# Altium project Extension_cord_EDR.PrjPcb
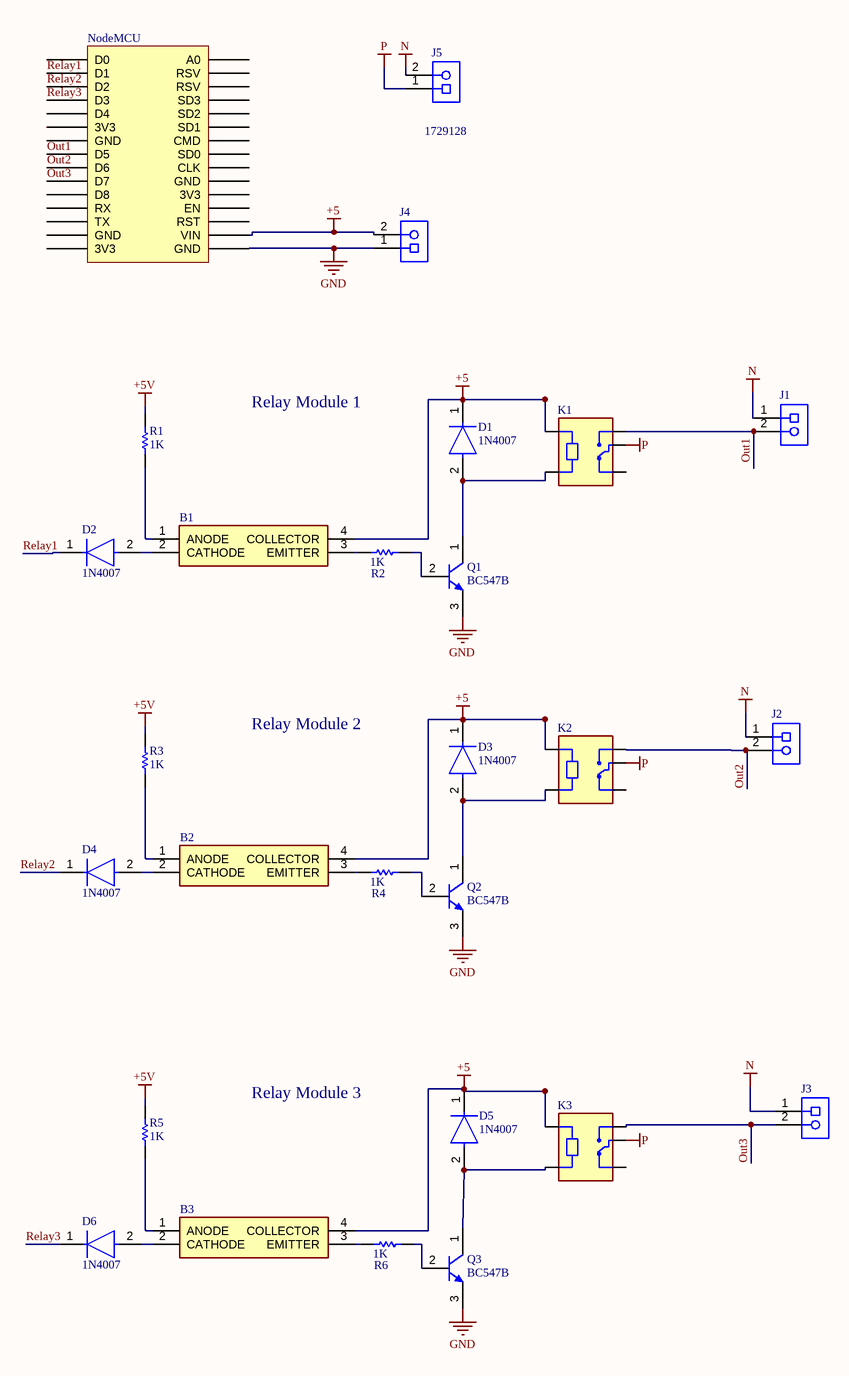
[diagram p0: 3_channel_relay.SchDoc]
1 sheet, 27 parts. Net scope: global (net labels, ports and power ports of the same name join across sheets).
Board file: PCB1.PcbDoc

## Sheet 3_channel_relay.SchDoc
size B portrait; SheetNumber: 1; SheetTotal: 1

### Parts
B1  PC817X2NSZ0F  [DIP762W60P254L458H400Q4N]  (value not drawn)
B2  PC817X2NSZ0F  [DIP762W60P254L458H400Q4N]  (value not drawn)
B3  PC817X2NSZ0F  [DIP762W60P254L458H400Q4N]  (value not drawn)
D1  1N4007  [FP-1N4007-MFG]
D2  1N4007  [FP-1N4007-MFG]
D3  1N4007  [FP-1N4007-MFG]
D4  1N4007  [FP-1N4007-MFG]
D5  1N4007  [FP-1N4007-MFG]
D6  1N4007  [FP-1N4007-MFG]
J1  1729128  [PHOE-1729128-2_V]  (value not drawn)
J2  1729128  [PHOE-1729128-2_V]  (value not drawn)
J3  1729128  [PHOE-1729128-2_V]  (value not drawn)
J4  (no value)  [PHOE-1729128-2_V]
J5  1729128  [PHOE-1729128-2_V]
K1  SRD-05VDC-SL-C  [RELAY_SRD-05VDC-SL-C]  (value not drawn)
K2  SRD-05VDC-SL-C  [RELAY_SRD-05VDC-SL-C]  (value not drawn)
K3  SRD-05VDC-SL-C  [RELAY_SRD-05VDC-SL-C]  (value not drawn)
NodeMCU  NodeMCU V1.0 ESP-12E  [NodeMCU V1.0 ESP-12E]  (value not drawn)
Q1  BC547B  [ONSC-TO-92-3-29-11]
Q2  BC547B  [ONSC-TO-92-3-29-11]
Q3  BC547B  [ONSC-TO-92-3-29-11]
R1  1K  [RESA60-630X240]
R2  1K  [RESA60-630X240]
R3  1K  [RESA60-630X240]
R4  1K  [RESA60-630X240]
R5  1K  [RESA60-630X240]
R6  1K  [RESA60-630X240]

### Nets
+5: B1.4(COLLECTOR) B2.4(COLLECTOR) B3.4(COLLECTOR) D1.1(C) D3.1(C) D5.1(C) J4.2 K1.A1 K2.A1 K3.A1 NodeMCU.VIN
+5V: R1.2 R3.2 R5.2
GND: J4.1 NodeMCU.GND Q1.3(E) Q2.3(E) Q3.3(E)
N: J1.1 J2.1 J3.1 J5.2
P: J5.1 K1.COM K2.COM K3.COM
Out1: J1.2 K1.NC NodeMCU.D5
Out2: J2.2 K2.NC NodeMCU.D6
Out3: J3.2 K3.NC NodeMCU.D7
Relay1: D2.1(C) NodeMCU.D1
Relay2: D4.1(C) NodeMCU.D2
Relay3: D6.1(C) NodeMCU.D3
NetB1_1: B1.1(ANODE) R1.1
NetB1_2: B1.2(CATHODE) D2.2(A)
NetB1_3: B1.3(EMITTER) R2.2
NetB2_1: B2.1(ANODE) R3.1
NetB2_2: B2.2(CATHODE) D4.2(A)
NetB2_3: B2.3(EMITTER) R4.2
NetB3_1: B3.1(ANODE) R5.1
NetB3_2: B3.2(CATHODE) D6.2(A)
NetB3_3: B3.3(EMITTER) R6.2
NetD1_2: D1.2(A) K1.A2 Q1.1(C)
NetD3_2: D3.2(A) K2.A2 Q2.1(C)
NetD5_2: D5.2(A) K3.A2 Q3.1(C)
NetQ1_2: Q1.2(B) R2.1
NetQ2_2: Q2.2(B) R4.1
NetQ3_2: Q3.2(B) R6.1

Not connected (* = marked no-connect by the designer): K1 NO; K2 NO; K3 NO; NodeMCU 3V3 A0 CLK CMD D0 D4 D8 EN RST RSV RX SD0 SD1 SD2 SD3 TX

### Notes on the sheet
- Relay Module 1
- Relay Module 2
- Relay Module 3

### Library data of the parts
B1-B3 = PC817X2NSZ0F: Photocoupler 1-CH Transistor 4-Pin PDIP Sharp PC817X2NSZ0F DC Input Transistor Output Optocoupler, Through Hole, 4-Pin PDIP; Manufacturer_Name: Sharp Microelectronics; Geometry.Height: 4mm
D1-D6 = CMP-123542-000001-1: Rectifier diode 1000 V 1 A DO-41, ,; Manufacturer: Diotec; Max Surge Forward Current: 27A; Forward Current: 1A; Max Junction Temp: +175°C; Reverse Voltage: 1000V; Value: 15pF; Peak Reverse Current: 5uA
J1-J3 J5 = CMP-2000-05815-1: PCB Terminal Block, 13.5 A, 400 V, 2-Pin THD, RoHS, Bulk; Manufacturer: Phoenix Contact; Package Version: 03/2015; No. of Rows: 1; Pitch: 5.08mm; No. of Positions: 2; Voltage Rating: 400V; Current Rating: 13500mA
J4 = CMP-2000-05815-1: PCB Terminal Block, 13.5 A, 400 V, 2-Pin THD, RoHS, Bulk; PartNumber: 1729128; Manufacturer: Phoenix Contact; Package Version: 03/2015; No. of Rows: 1; Pitch: 5.08mm; No. of Positions: 2; Voltage Rating: 400V; Current Rating: 13500mA
K1-K3 = SRD-05VDC-SL-C: 5V Trigger Relay Module For Arduino And Raspberry Pi 5V Trigger Relay Module For Arduino And Raspberry Pi; MF: Songle Relay
NodeMCU = NodeMCU V1.0 ESP-12E: NodeMCU V1.0 ESP8266 (ESP-12E)
Q1-Q3 = CMP-1048-01467-1: Amplifier Transistor, NPN Silicon, 3-Pin TO-92, Bulk Box; Manufacturer: On Semiconductor; IC Continuous (A): 0.1; fT Min (MHz): 150
R1-R6 = CMP-1659-00075-1: Axial Resistor, 1 KOhm, +/- 1%, 250 mW, -55 to 155 degC, 2-Pin THD, RoHS, Bulk; Voltage Rating: 250 V; Resistance: 10 kohm; Power Rating: 250 mW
